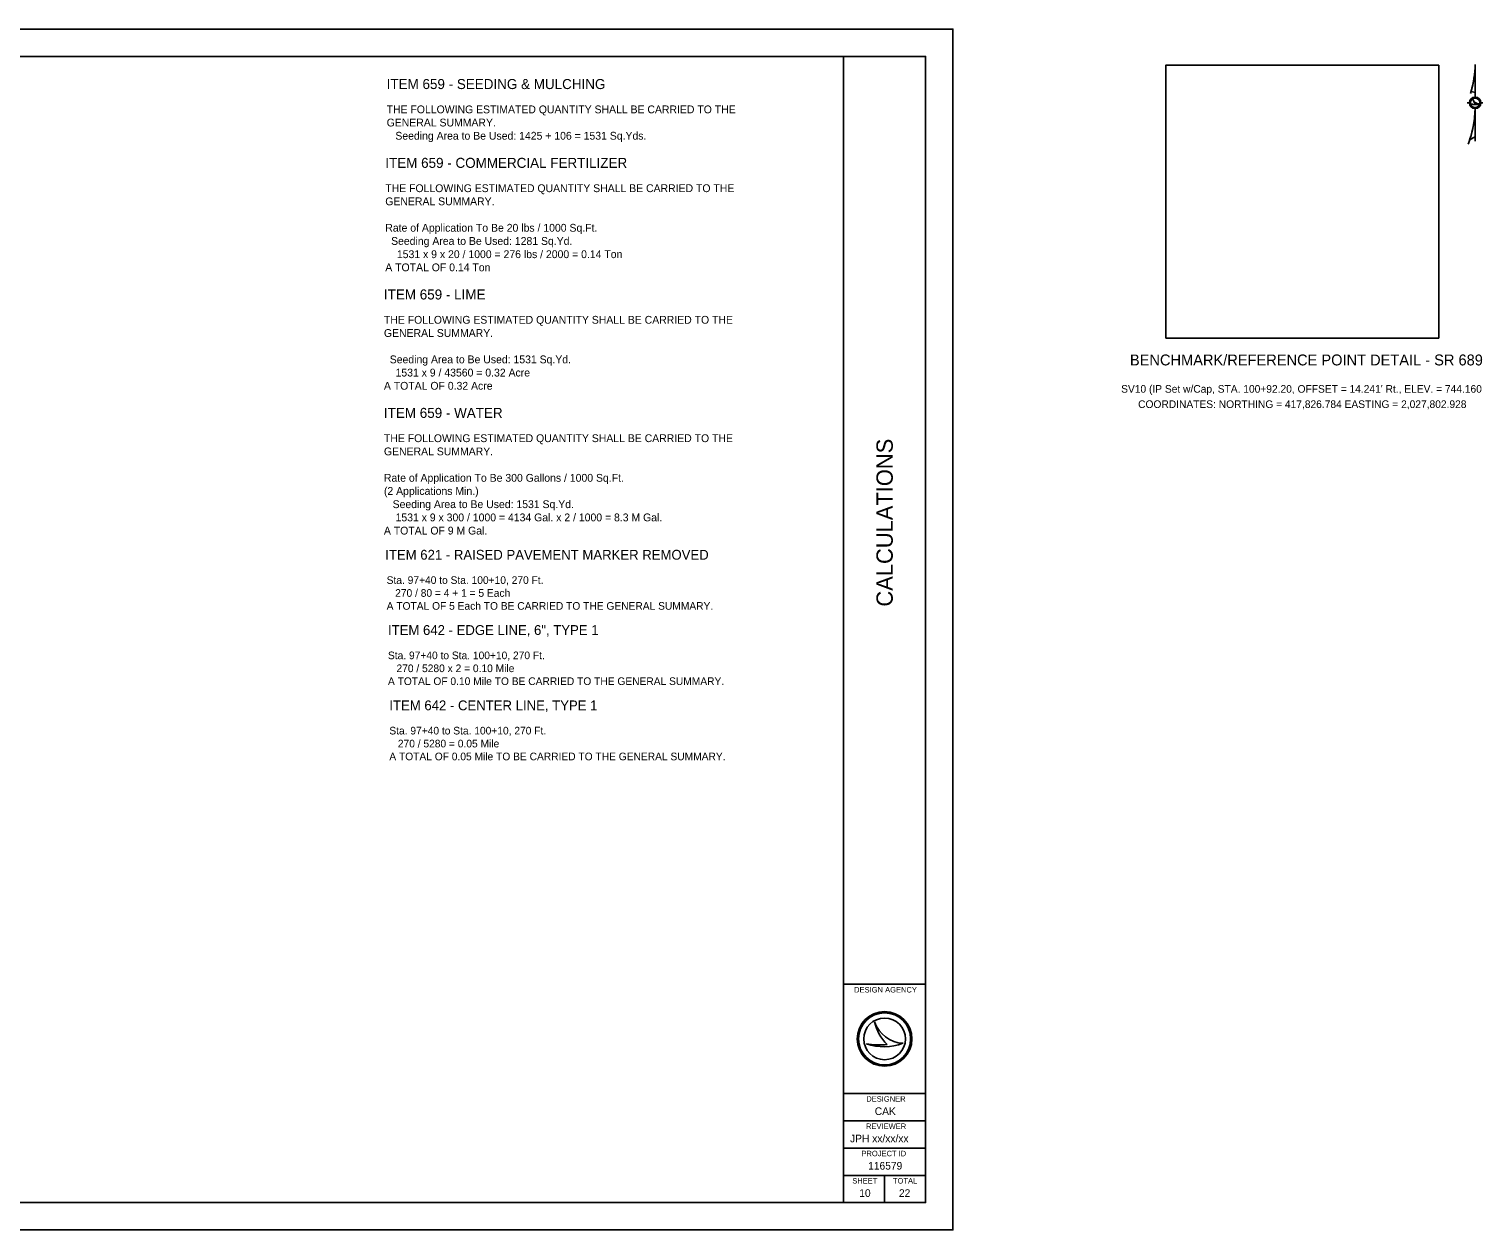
# Model space of a CAD drawing. Extents: x -9.6 to 43.7, y 0 to 24.6.
# Drawn here: x 17.08 to 43.71, y 0 to 22 of the extents above; entities that cross this region are included whole.
import ezdxf

# ---------------------------------------------------------------- set-up
doc = ezdxf.new("R2010")
doc.units = 0
for name, color, linetype in [('Default', 7, 'Continuous'), ('Level 1', 7, 'Continuous'), ('SH_Border', 7, 'Continuous'), ('SH_Cut_Line', 7, 'Continuous'), ('SH_Data', 7, 'Continuous')]:
    doc.layers.add(name, color=color, linetype=linetype)

msp = doc.modelspace()

# ---------------------------------------------------------------- linework, layer by layer
at = {"layer": 'SH_Border'}
for p, q in [((32, 0.5), (32, 21.5)), ((32, 4.5), (33.5, 4.5)), ((32, 2.5), (33.5, 2.5)), ((32, 2), (33.5, 2)), ((32, 1.5), (33.5, 1.5)), ((32, 1), (33.5, 1))]:
    msp.add_line(p, q, dxfattribs=at)
msp.add_lwpolyline([(1.5, 21.5), (33.5, 21.5), (33.5, 0.5), (1.5, 0.5)], close=True, dxfattribs=at)
at = {"layer": 'SH_Cut_Line'}
msp.add_lwpolyline([(0, 0), (34, 0), (34, 22), (0, 22)], close=True, dxfattribs=at)
at = {"layer": 'SH_Data'}
for p, q in [((43.567, 20.755), (43.567, 21.353)), ((43.492, 20.856), (43.567, 20.835)), ((43.424, 20.649), (43.461, 20.649)), ((43.567, 19.946), (43.567, 20.544)), ((43.672, 20.649), (43.71, 20.649)), ((43.567, 20.028), (43.466, 19.968)), ((32.567, 3.81), (32.567, 3.81)), ((32.75, 3.5), (32.75, 3.5)), ((32.417, 3.41), (32.417, 3.41)), ((33.087, 3.419), (33.087, 3.419)), ((32.75, 0.5), (32.75, 1)), ((32.375, 0.675), (32.375, 0.675))]:
    msp.add_line(p, q, dxfattribs=at)
msp.add_lwpolyline([(37.9, 16.338), (42.9, 16.338), (42.9, 21.338), (37.9, 21.338)], close=True, dxfattribs=at)
for points in [[(43.491, 20.856), (43.492, 20.856), (43.567, 20.835), (43.567, 21.353)], [(43.466, 19.968), (43.567, 20.028), (43.567, 20.544)]]:
    msp.add_lwpolyline(points, dxfattribs=at)
for centre, radius in [((43.567, 20.649), 0.105), ((43.567, 20.649), 0.0867), ((32.75, 3.5), 0.5), ((32.75, 3.5), 0.477), ((32.75, 3.5), 0.477), ((32.75, 3.5), 0.382)]:
    msp.add_circle(centre, radius, dxfattribs=at)
for centre, radius, start, end in [((41.719, 21.379), 1.848, 342.4153, 359.1947), ((41.719, 21.379), 1.848, 343.5754, 359.1947), ((41.719, 20.57), 1.848, 338.5054, 359.1947), ((41.719, 20.57), 1.848, 340.9936, 359.1947), ((43.561, 20.827), 0.212, 252.4874, 291.486), ((43.541, 20.889), 0.268, 260.7277, 277.8734), ((43.64, 20.749), 0.119, 199.1574, 269.3709), ((43.691, 20.747), 0.168, 192.8556, 227.3141), ((33.116, 3.998), 0.58, 198.9257, 198.9319), ((33.347, 3.97), 0.796, 191.6379, 191.6421), ((33.116, 3.998), 0.58, 198.9319, 267.1657), ((33.347, 3.97), 0.796, 191.6421, 226.0947), ((32.739, 4.37), 1.013, 251.4576, 290.0832), ((32.648, 4.654), 1.266, 259.4964, 259.4995), ((32.739, 4.37), 1.013, 251.4527, 251.4576), ((32.648, 4.654), 1.266, 259.4995, 276.6672)]:
    msp.add_arc(centre, radius, start, end, dxfattribs=at)

# ---------------------------------------------------------------- texts
at = {"layer": 'Default'}
for s, height, p in [('ITEM 659 - SEEDING & MULCHING', 0.18406, (23.629, 20.901)), ('ITEM 659 - COMMERCIAL FERTILIZER', 0.18406, (23.604, 19.457)), ('ITEM 659 - LIME', 0.18406, (23.579, 17.046)), ('ITEM 659 - WATER', 0.18406, (23.579, 14.876)), ('ITEM 621 - RAISED PAVEMENT MARKER REMOVED', 0.18, (23.603, 12.279)), ('ITEM 642 - EDGE LINE, 6", TYPE 1', 0.18, (23.653, 10.9)), ('ITEM 642 - CENTER LINE, TYPE 1', 0.18, (23.678, 9.52))]:
    msp.add_text(s, height=height, dxfattribs=at).set_placement(p)
at = {"layer": 'Level 1'}
for s, height, p in [('THE FOLLOWING ESTIMATED QUANTITY SHALL BE CARRIED TO THE', 0.14317, (23.629, 20.457)), ('GENERAL SUMMARY.', 0.14317, (23.629, 20.216)), ('   Seeding Area to Be Used: 1425 + 106 = 1531 Sq.Yds.', 0.14317, (23.629, 19.974)), ('THE FOLLOWING ESTIMATED QUANTITY SHALL BE CARRIED TO THE', 0.14317, (23.604, 19.013)), ('GENERAL SUMMARY.', 0.14317, (23.604, 18.772)), ('Rate of Application To Be 20 lbs / 1000 Sq.Ft.', 0.14317, (23.604, 18.288)), ('  Seeding Area to Be Used: 1281 Sq.Yd.', 0.14317, (23.604, 18.046)), ('    1531 x 9 x 20 / 1000 = 276 lbs / 2000 = 0.14 Ton', 0.14317, (23.604, 17.804)), ('A TOTAL OF 0.14 Ton', 0.14317, (23.604, 17.563)), ('THE FOLLOWING ESTIMATED QUANTITY SHALL BE CARRIED TO THE', 0.14317, (23.579, 16.602)), ('GENERAL SUMMARY.', 0.14317, (23.579, 16.36)), ('  Seeding Area to Be Used: 1531 Sq.Yd.', 0.14317, (23.579, 15.877)), ('    1531 x 9 / 43560 = 0.32 Acre', 0.14317, (23.579, 15.635)), ('A TOTAL OF 0.32 Acre', 0.14317, (23.579, 15.393)), ('THE FOLLOWING ESTIMATED QUANTITY SHALL BE CARRIED TO THE', 0.14317, (23.579, 14.433)), ('GENERAL SUMMARY.', 0.14317, (23.579, 14.191)), ('Rate of Application To Be 300 Gallons / 1000 Sq.Ft.', 0.14317, (23.579, 13.707)), ('(2 Applications Min.)', 0.14317, (23.579, 13.466)), ('   Seeding Area to Be Used: 1531 Sq.Yd.', 0.14317, (23.579, 13.224)), ('    1531 x 9 x 300 / 1000 = 4134 Gal. x 2 / 1000 = 8.3 M Gal.', 0.14317, (23.579, 12.982)), ('A TOTAL OF 9 M Gal.', 0.14317, (23.579, 12.74)), ('Sta. 97+40 to Sta. 100+10, 270 Ft.', 0.14, (23.629, 11.835)), ('   270 / 80 = 4 + 1 = 5 Each', 0.14, (23.629, 11.599)), ('A TOTAL OF 5 Each TO BE CARRIED TO THE GENERAL SUMMARY.', 0.14, (23.629, 11.362)), ('Sta. 97+40 to Sta. 100+10, 270 Ft.', 0.14, (23.653, 10.456)), ('A TOTAL OF 0.10 Mile TO BE CARRIED TO THE GENERAL SUMMARY.', 0.14, (23.653, 9.983)), ('   270 / 5280 x 2 = 0.10 Mile', 0.14, (23.653, 10.219)), ('Sta. 97+40 to Sta. 100+10, 270 Ft.', 0.14, (23.678, 9.077)), ('   270 / 5280 = 0.05 Mile', 0.14, (23.678, 8.84)), ('A TOTAL OF 0.05 Mile TO BE CARRIED TO THE GENERAL SUMMARY.', 0.14, (23.678, 8.604))]:
    msp.add_text(s, height=height, dxfattribs=at).set_placement(p)
at = {"layer": 'SH_Data'}
for s, height, p in [('BENCHMARK/REFERENCE POINT DETAIL - SR 689', 0.2, (37.244, 15.838)), ("SV10 (IP Set w/Cap, STA. 100+92.20, OFFSET = 14.241' Rt., ELEV. = 744.160", 0.14, (37.083, 15.338)), ('COORDINATES: NORTHING = 417,826.784 EASTING = 2,027,802.928', 0.14, (37.394, 15.058)), ('DESIGN AGENCY', 0.1, (32.191, 4.35)), ('DESIGNER', 0.1, (32.414, 2.35)), ('CAK', 0.14, (32.57, 2.105)), ('REVIEWER', 0.1, (32.409, 1.85)), ('JPH xx/xx/xx', 0.14, (32.117, 1.605)), ('PROJECT ID', 0.1, (32.325, 1.35)), ('116579', 0.14, (32.449, 1.105)), ('SHEET', 0.1, (32.158, 0.85)), ('TOTAL', 0.1, (32.903, 0.85)), ('10', 0.14, (32.286, 0.605)), ('22', 0.14, (33.013, 0.605))]:
    msp.add_text(s, height=height, dxfattribs=at).set_placement(p)
msp.add_text('CALCULATIONS', height=0.3, rotation=90, dxfattribs=at).set_placement((32.9, 11.419))

doc.saveas('drawing.dxf')
